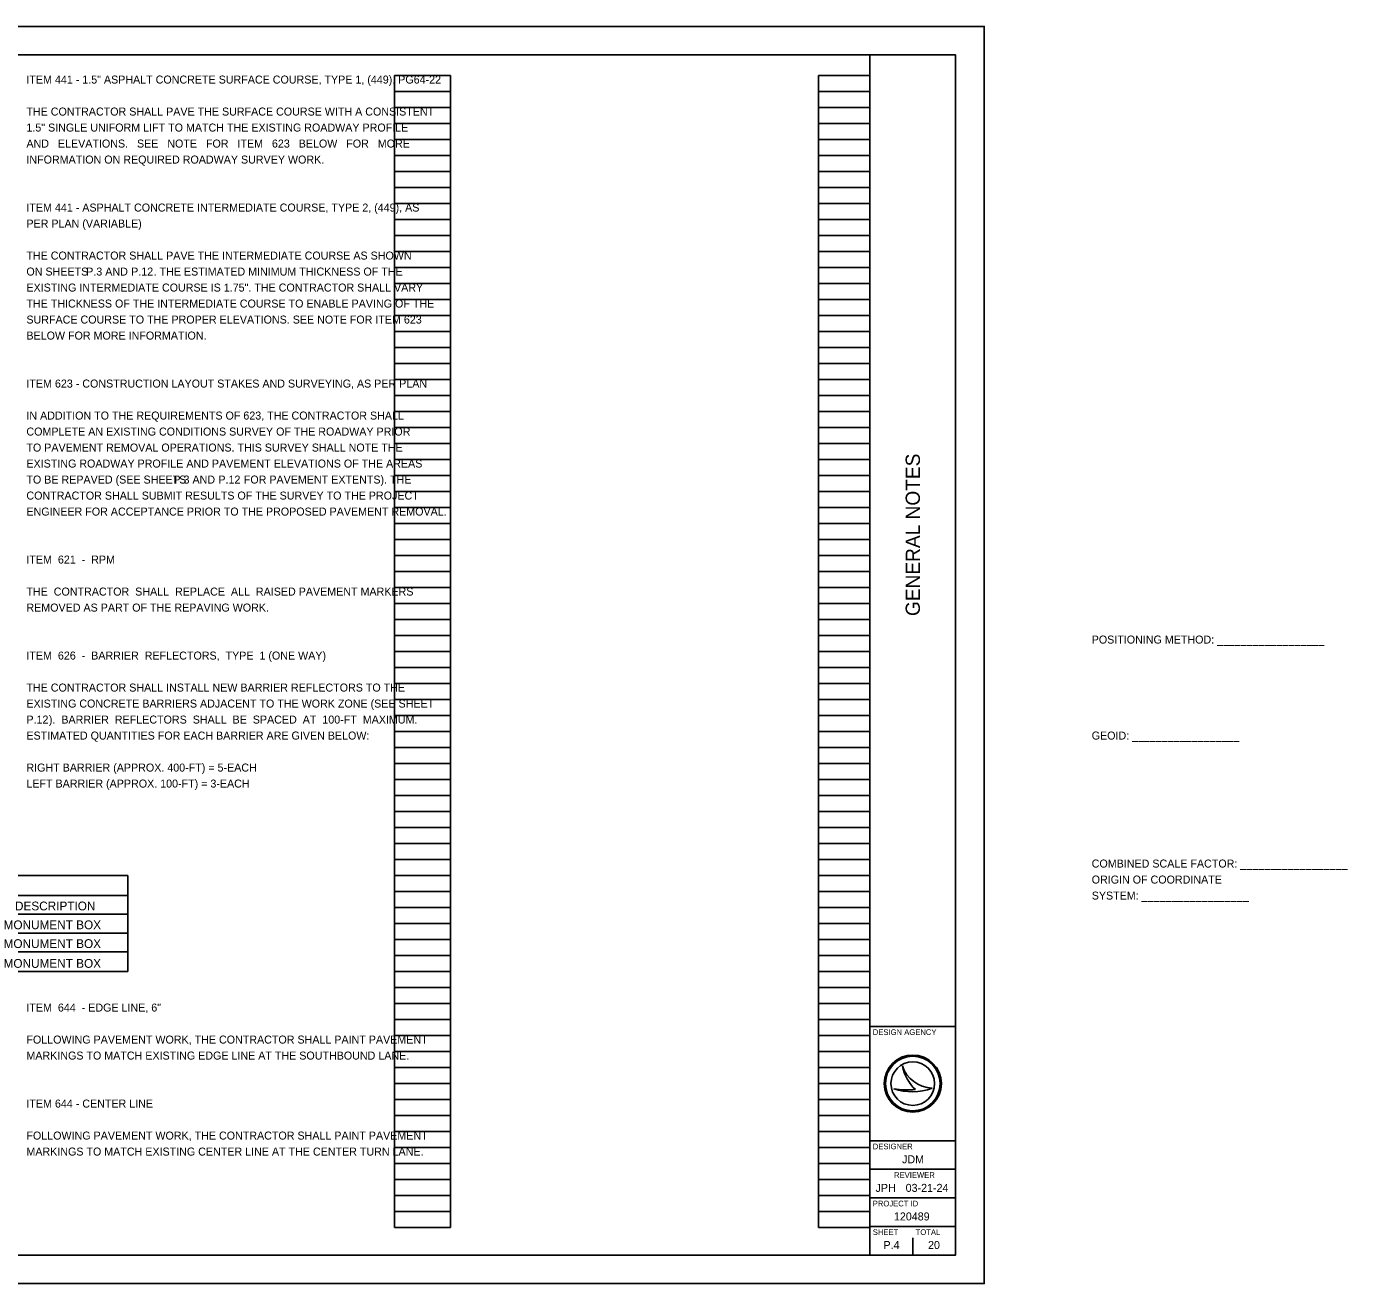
# Model space of a CAD drawing. Extents: x -9.1 to 40.4, y -15.8 to 28.7.
# Drawn here: x 17.24 to 40.36, y 0 to 22 of the extents above; entities that cross this region are included whole.
import ezdxf

# ---------------------------------------------------------------- set-up
doc = ezdxf.new("R2010")
doc.units = 0
for name, color, linetype in [('SH_Border', 7, 'Continuous'), ('SH_Cut_Line', 7, 'Continuous'), ('SH_Data', 7, 'Continuous'), ('SH_Text', 7, 'Continuous')]:
    doc.layers.add(name, color=color, linetype=linetype)

msp = doc.modelspace()

# ---------------------------------------------------------------- linework, layer by layer
at = {"layer": 'SH_Border'}
for p, q in [((32, 0.5), (32, 21.5)), ((32, 4.5), (33.5, 4.5)), ((32, 2.5), (33.5, 2.5)), ((32, 2), (33.5, 2)), ((32, 1.5), (33.5, 1.5)), ((32, 1), (33.5, 1))]:
    msp.add_line(p, q, dxfattribs=at)
msp.add_lwpolyline([(1.5, 21.5), (33.5, 21.5), (33.5, 0.5), (1.5, 0.5)], close=True, dxfattribs=at)
at = {"layer": 'SH_Cut_Line'}
msp.add_lwpolyline([(0, 0), (34, 0), (34, 22), (0, 22)], close=True, dxfattribs=at)
at = {"layer": 'SH_Data'}
for p, q in [((23.68, 0.98), (23.68, 21.14)), ((23.68, 21.14), (24.66, 21.14)), ((24.66, 0.98), (24.66, 21.14)), ((31.1, 0.98), (31.1, 21.14)), ((31.1, 21.14), (32, 21.14)), ((32, 0.98), (32, 21.14)), ((23.68, 20.86), (24.66, 20.86)), ((31.1, 20.86), (32, 20.86)), ((23.68, 20.58), (24.66, 20.58)), ((31.1, 20.58), (32, 20.58)), ((23.68, 20.3), (24.66, 20.3)), ((31.1, 20.3), (32, 20.3)), ((23.68, 20.02), (24.66, 20.02)), ((31.1, 20.02), (32, 20.02)), ((23.68, 19.74), (24.66, 19.74)), ((31.1, 19.74), (32, 19.74)), ((23.68, 19.46), (24.66, 19.46)), ((31.1, 19.46), (32, 19.46)), ((23.68, 19.18), (24.66, 19.18)), ((31.1, 19.18), (32, 19.18)), ((23.68, 18.9), (24.66, 18.9)), ((31.1, 18.9), (32, 18.9)), ((23.68, 18.62), (24.66, 18.62)), ((31.1, 18.62), (32, 18.62)), ((23.68, 18.34), (24.66, 18.34)), ((31.1, 18.34), (32, 18.34)), ((23.68, 18.06), (24.66, 18.06)), ((31.1, 18.06), (32, 18.06)), ((23.68, 17.78), (24.66, 17.78)), ((31.1, 17.78), (32, 17.78)), ((23.68, 17.5), (24.66, 17.5)), ((31.1, 17.5), (32, 17.5)), ((23.68, 17.22), (24.66, 17.22)), ((31.1, 17.22), (32, 17.22)), ((23.68, 16.94), (24.66, 16.94)), ((31.1, 16.94), (32, 16.94)), ((23.68, 16.66), (24.66, 16.66)), ((31.1, 16.66), (32, 16.66)), ((23.68, 16.38), (24.66, 16.38)), ((31.1, 16.38), (32, 16.38)), ((23.68, 16.1), (24.66, 16.1)), ((31.1, 16.1), (32, 16.1)), ((23.68, 15.82), (24.66, 15.82)), ((31.1, 15.82), (32, 15.82)), ((23.68, 15.54), (24.66, 15.54)), ((31.1, 15.54), (32, 15.54)), ((23.68, 15.26), (24.66, 15.26)), ((31.1, 15.26), (32, 15.26)), ((23.68, 14.98), (24.66, 14.98)), ((31.1, 14.98), (32, 14.98)), ((23.68, 14.7), (24.66, 14.7)), ((31.1, 14.7), (32, 14.7)), ((23.68, 14.42), (24.66, 14.42)), ((31.1, 14.42), (32, 14.42)), ((23.68, 14.14), (24.66, 14.14)), ((31.1, 14.14), (32, 14.14)), ((23.68, 13.86), (24.66, 13.86)), ((31.1, 13.86), (32, 13.86)), ((23.68, 13.58), (24.66, 13.58)), ((31.1, 13.58), (32, 13.58)), ((23.68, 13.3), (24.66, 13.3)), ((31.1, 13.3), (32, 13.3)), ((23.68, 13.02), (24.66, 13.02)), ((31.1, 13.02), (32, 13.02)), ((23.68, 12.74), (24.66, 12.74)), ((31.1, 12.74), (32, 12.74)), ((23.68, 12.46), (24.66, 12.46)), ((31.1, 12.46), (32, 12.46)), ((23.68, 12.18), (24.66, 12.18)), ((31.1, 12.18), (32, 12.18)), ((23.68, 11.9), (24.66, 11.9)), ((31.1, 11.9), (32, 11.9)), ((23.68, 11.62), (24.66, 11.62)), ((31.1, 11.62), (32, 11.62)), ((23.68, 11.34), (24.66, 11.34)), ((31.1, 11.34), (32, 11.34)), ((23.68, 11.06), (24.66, 11.06)), ((31.1, 11.06), (32, 11.06)), ((23.68, 10.78), (24.66, 10.78)), ((31.1, 10.78), (32, 10.78)), ((23.68, 10.5), (24.66, 10.5)), ((31.1, 10.5), (32, 10.5)), ((23.68, 10.22), (24.66, 10.22)), ((31.1, 10.22), (32, 10.22)), ((23.68, 9.94), (24.66, 9.94)), ((31.1, 9.94), (32, 9.94)), ((23.68, 9.66), (24.66, 9.66)), ((31.1, 9.66), (32, 9.66)), ((23.68, 9.38), (24.66, 9.38)), ((31.1, 9.38), (32, 9.38)), ((23.68, 9.1), (24.66, 9.1)), ((31.1, 9.1), (32, 9.1)), ((23.68, 8.82), (24.66, 8.82)), ((31.1, 8.82), (32, 8.82)), ((23.68, 8.54), (24.66, 8.54)), ((31.1, 8.54), (32, 8.54)), ((23.68, 8.26), (24.66, 8.26)), ((31.1, 8.26), (32, 8.26)), ((23.68, 7.98), (24.66, 7.98)), ((31.1, 7.98), (32, 7.98)), ((23.68, 7.7), (24.66, 7.7)), ((31.1, 7.7), (32, 7.7)), ((23.68, 7.42), (24.66, 7.42)), ((31.1, 7.42), (32, 7.42)), ((23.68, 7.14), (24.66, 7.14)), ((31.1, 7.14), (32, 7.14)), ((23.68, 6.86), (24.66, 6.86)), ((31.1, 6.86), (32, 6.86)), ((23.68, 6.58), (24.66, 6.58)), ((31.1, 6.58), (32, 6.58)), ((23.68, 6.3), (24.66, 6.3)), ((31.1, 6.3), (32, 6.3)), ((23.68, 6.02), (24.66, 6.02)), ((31.1, 6.02), (32, 6.02)), ((23.68, 5.74), (24.66, 5.74)), ((31.1, 5.74), (32, 5.74)), ((23.68, 5.46), (24.66, 5.46)), ((31.1, 5.46), (32, 5.46)), ((23.68, 5.18), (24.66, 5.18)), ((31.1, 5.18), (32, 5.18)), ((23.68, 4.9), (24.66, 4.9)), ((31.1, 4.9), (32, 4.9)), ((23.68, 4.62), (24.66, 4.62)), ((31.1, 4.62), (32, 4.62)), ((23.68, 4.34), (24.66, 4.34)), ((31.1, 4.34), (32, 4.34)), ((23.68, 4.06), (24.66, 4.06)), ((31.1, 4.06), (32, 4.06)), ((23.68, 3.78), (24.66, 3.78)), ((31.1, 3.78), (32, 3.78)), ((32.567, 3.81), (32.567, 3.81)), ((23.68, 3.5), (24.66, 3.5)), ((31.1, 3.5), (32, 3.5)), ((32.75, 3.5), (32.75, 3.5)), ((32.417, 3.41), (32.417, 3.41)), ((33.087, 3.419), (33.087, 3.419)), ((23.68, 3.22), (24.66, 3.22)), ((31.1, 3.22), (32, 3.22)), ((23.68, 2.94), (24.66, 2.94)), ((31.1, 2.94), (32, 2.94)), ((23.68, 2.66), (24.66, 2.66)), ((31.1, 2.66), (32, 2.66)), ((23.68, 2.38), (24.66, 2.38)), ((31.1, 2.38), (32, 2.38)), ((23.68, 2.1), (24.66, 2.1)), ((31.1, 2.1), (32, 2.1)), ((23.68, 1.82), (24.66, 1.82)), ((31.1, 1.82), (32, 1.82)), ((23.68, 1.54), (24.66, 1.54)), ((31.1, 1.54), (32, 1.54)), ((23.68, 1.26), (24.66, 1.26)), ((31.1, 1.26), (32, 1.26)), ((23.68, 0.98), (24.66, 0.98)), ((31.1, 0.98), (32, 0.98)), ((32.75, 0.5), (32.75, 0.8)), ((32.375, 0.675), (32.375, 0.675))]:
    msp.add_line(p, q, dxfattribs=at)
for radius in [0.5, 0.477, 0.477, 0.382]:
    msp.add_circle((32.75, 3.5), radius, dxfattribs=at)
for centre, radius, start, end in [((33.116, 3.998), 0.58, 198.9257, 198.9319), ((33.347, 3.97), 0.796, 191.6379, 191.6421), ((33.116, 3.998), 0.58, 198.9319, 267.1657), ((33.347, 3.97), 0.796, 191.6421, 226.0947), ((32.739, 4.37), 1.013, 251.4576, 290.0832), ((32.648, 4.654), 1.266, 259.4964, 259.4995), ((32.739, 4.37), 1.013, 251.4527, 251.4576), ((32.648, 4.654), 1.266, 259.4995, 276.6672)]:
    msp.add_arc(centre, radius, start, end, dxfattribs=at)
at = {"layer": 'SH_Text'}
for p, q in [((9.33, 7.14), (19.015, 7.14)), ((19.015, 7.14), (19.015, 5.46)), ((9.33, 6.794), (19.015, 6.794)), ((9.33, 6.465), (19.015, 6.465)), ((9.33, 6.135), (19.015, 6.135)), ((9.33, 5.806), (19.015, 5.806)), ((9.33, 5.46), (19.015, 5.46))]:
    msp.add_line(p, q, dxfattribs=at)

# ---------------------------------------------------------------- texts
at = {"layer": 'SH_Data'}
msp.add_text('GENERAL NOTES', height=0.25, rotation=90, dxfattribs=at).set_placement((32.875, 11.682))
for s, height, p in [('DESIGN AGENCY', 0.1, (32.05, 4.35)), ('DESIGNER', 0.1, (32.05, 2.35)), ('JDM', 0.14, (32.562, 2.105)), ('REVIEWER', 0.1, (32.422, 1.85)), ('JPH', 0.14, (32.098, 1.605)), ('03-21-24', 0.14, (32.625, 1.605)), ('PROJECT ID', 0.1, (32.05, 1.35)), ('120489', 0.14, (32.42, 1.105)), ('SHEET', 0.1, (32.05, 0.85)), ('TOTAL', 0.1, (32.8, 0.85)), ('P.4', 0.14, (32.237, 0.605)), ('20', 0.14, (33.017, 0.605))]:
    msp.add_text(s, height=height, dxfattribs=at).set_placement(p)
at = {"layer": 'SH_Text'}
for s, height, p in [('ITEM 441 - 1.5" ASPHALT CONCRETE SURFACE COURSE, TYPE 1, (449), PG64-22', 0.14, (17.24, 21)), ('THE CONTRACTOR SHALL PAVE THE SURFACE COURSE WITH A CONSISTENT', 0.14, (17.24, 20.44)), ('1.5" SINGLE UNIFORM LIFT TO MATCH THE EXISTING ROADWAY PROFILE', 0.14, (17.24, 20.16)), ('AND   ELEVATIONS.   SEE   NOTE   FOR   ITEM   623   BELOW   FOR   MORE', 0.14, (17.24, 19.88)), ('INFORMATION ON REQUIRED ROADWAY SURVEY WORK.', 0.14, (17.24, 19.6)), ('ITEM 441 - ASPHALT CONCRETE INTERMEDIATE COURSE, TYPE 2, (449), AS', 0.14, (17.24, 18.76)), ('PER PLAN (VARIABLE)', 0.14, (17.24, 18.48)), ('THE CONTRACTOR SHALL PAVE THE INTERMEDIATE COURSE AS SHOWN', 0.14, (17.24, 17.92)), ('ON SHEETS ', 0.14, (17.24, 17.64)), ('P.3', 0.14, (18.286, 17.64)), (' A', 0.14, (18.567, 17.64)), ('ND ', 0.14, (18.745, 17.64)), ('P.12', 0.14, (19.073, 17.64)), ('. THE ESTIMATED MINIMUM THICKNESS OF THE', 0.14, (19.466, 17.64)), ('EXISTING INTERMEDIATE COURSE IS 1.75". THE CONTRACTOR SHALL VARY', 0.14, (17.24, 17.36)), ('THE THICKNESS OF THE INTERMEDIATE COURSE TO ENABLE PAVING OF THE', 0.14, (17.24, 17.08)), ('SURFACE COURSE TO THE PROPER ELEVATIONS. SEE NOTE FOR ITEM 623', 0.14, (17.24, 16.8)), ('BELOW FOR MORE INFORMATION.', 0.14, (17.24, 16.52)), ('ITEM 623 - CONSTRUCTION LAYOUT STAKES AND SURVEYING, AS PER PLAN', 0.14, (17.24, 15.68)), ('IN ADDITION TO THE REQUIREMENTS OF 623, THE CONTRACTOR SHALL', 0.14, (17.24, 15.12)), ('COMPLETE AN EXISTING CONDITIONS SURVEY OF THE ROADWAY PRIOR', 0.14, (17.24, 14.84)), ('TO PAVEMENT REMOVAL OPERATIONS. THIS SURVEY SHALL NOTE THE', 0.14, (17.24, 14.56)), ('EXISTING ROADWAY PROFILE AND PAVEMENT ELEVATIONS OF THE AREAS ', 0.14, (17.24, 14.28)), ('TO BE REPAVED (SEE SHEETS ', 0.14, (17.24, 14)), ('P.3', 0.14, (19.812, 14)), (' AND ', 0.14, (20.094, 14)), ('P.12', 0.14, (20.599, 14)), (' FOR PAVEMENT EXTENTS). THE', 0.14, (20.992, 14)), ('CONTRACTOR SHALL SUBMIT RESULTS OF THE SURVEY TO THE PROJECT', 0.14, (17.24, 13.72)), ('ENGINEER FOR ACCEPTANCE PRIOR TO THE PROPOSED PAVEMENT REMOVAL.', 0.14, (17.24, 13.44)), ('ITEM  621  -  RPM', 0.14, (17.24, 12.6)), ('THE  CONTRACTOR  SHALL  REPLACE  ALL  RAISED PAVEMENT MARKERS', 0.14, (17.24, 12.04)), ('REMOVED AS PART OF THE REPAVING WORK.', 0.14, (17.24, 11.76)), ('POSITIONING METHOD: __________________', 0.14, (35.881, 11.2)), ('ITEM  626  -  BARRIER  REFLECTORS,  TYPE  1 (ONE WAY)', 0.14, (17.24, 10.92)), ('THE CONTRACTOR SHALL INSTALL NEW BARRIER REFLECTORS TO THE', 0.14, (17.24, 10.36)), ('EXISTING CONCRETE BARRIERS ADJACENT TO THE WORK ZONE (SEE SHEET', 0.14, (17.24, 10.08)), ('P.12', 0.14, (17.24, 9.8)), (').  BARRIER  REFLECTORS  SHALL  BE  SPACED  AT  100-FT  MAXIMUM.', 0.14, (17.633, 9.8)), ('ESTIMATED QUANTITIES FOR EACH BARRIER ARE GIVEN BELOW:', 0.14, (17.24, 9.52)), ('GEOID: __________________', 0.14, (35.881, 9.52)), ('RIGHT BARRIER (APPROX. 400-FT) = 5-EACH', 0.14, (17.24, 8.96)), ('LEFT BARRIER (APPROX. 100-FT) = 3-EACH', 0.14, (17.24, 8.68)), ('COMBINED SCALE FACTOR: __________________', 0.14, (35.881, 7.28)), ('ORIGIN OF COORDINATE', 0.14, (35.881, 7)), ('SYSTEM: __________________', 0.14, (35.881, 6.72)), ('DESCRIPTION', 0.154, (17.04, 6.531)), ('MONUMENT BOX', 0.154, (16.841, 6.201)), ('MONUMENT BOX', 0.154, (16.841, 5.872)), ('MONUMENT BOX', 0.154, (16.841, 5.526)), ('ITEM  644  - EDGE LINE, 6"', 0.14, (17.24, 4.76)), ('FOLLOWING PAVEMENT WORK, THE CONTRACTOR SHALL PAINT PAVEMENT', 0.14, (17.24, 4.2)), ('MARKINGS TO MATCH EXISTING EDGE LINE AT THE SOUTHBOUND LANE.', 0.14, (17.24, 3.92)), ('ITEM 644 - CENTER LINE', 0.14, (17.24, 3.08)), ('FOLLOWING PAVEMENT WORK, THE CONTRACTOR SHALL PAINT PAVEMENT', 0.14, (17.24, 2.52)), ('MARKINGS TO MATCH EXISTING CENTER LINE AT THE CENTER TURN LANE.', 0.14, (17.24, 2.24))]:
    msp.add_text(s, height=height, dxfattribs=at).set_placement(p)

doc.saveas('drawing.dxf')
